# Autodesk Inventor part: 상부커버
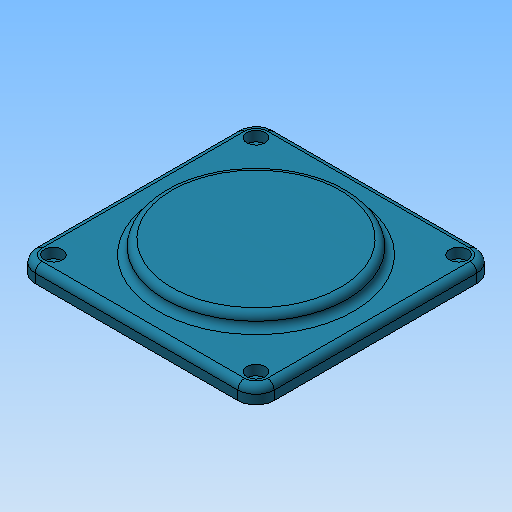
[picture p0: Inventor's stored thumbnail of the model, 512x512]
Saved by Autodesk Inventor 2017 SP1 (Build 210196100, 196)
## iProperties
Created: 2018-09
Part Number: 상부커버
Document SubType Name: Modeling
Density: 2.71 g/cm^3
Material: 알루미늄 6061
Mass: 284.928 g
Surface Area: 255.797 cm^2
Volume: 105.139 cm^3
Appearance: 터키옥색
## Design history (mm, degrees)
sketch "스케치5"
  geometry: L1 (-52.5, -52.5)-(52.5, -52.5); L2 (52.5, -52.5)-(52.5, 52.5); L3 (52.5, 52.5)-(-52.5, 52.5); L4 (-52.5, 52.5)-(-52.5, -52.5); L5 (-52.5, -52.5)-(52.5, 52.5); L6 (52.5, -52.5)-(-52.5, 52.5); 1 further point
  constraints: 12 end point, 2 midpoint, 2 parallel, 1 horizontal, 1 perpendicular
  dimensions: "d35" = 105 distance of L3.end L2.end; "d36" = 105 distance of L2.end L1.end
extrude "돌출4" new body sketch "스케치5" distance "d37" = 7; taper "d38" = 0 deg
fillet "모깎기4" dims "d39" = 8
sketch "스케치2"
  geometry: C1 r 40 at (0, 0); 2 further points
  constraints: 2 coincident, 1 centre point
  dimensions: "d4" = 80 diameter of C1
extrude "돌출3" join sketch "스케치2" distance "d5" = 6; taper "d6" = 0 deg
fillet "모깎기1" dims "d7" = 3
sketch "스케치4"
  geometry: L1 (52.5, -44.5)-(52.5, 44.5) reference; L2 (-44.5, -52.5)-(44.5, -52.5) reference; L3 (-52.5, 44.5)-(-52.5, -44.5) reference; L4 (44.5, 52.5)-(-44.5, 52.5) reference; A1 r 8 centre (44.5, 44.5) between (52.5, 44.5) and (44.5, 52.5) reference; A2 r 8 centre (44.5, -44.5) between (44.5, -52.5) and (52.5, -44.5) reference; A3 r 8 centre (-44.5, -44.5) between (-52.5, -44.5) and (-44.5, -52.5) reference; A4 r 8 centre (-44.5, 44.5) between (-44.5, 52.5) and (-52.5, 44.5) reference; 4 further points
  constraints: 4 coincident
hole "구멍3" sketch "스케치4" at (-44.5, 44.5), (-44.5, -44.5), (44.5, -44.5), (44.5, 44.5) diameter "d43" = 4.5; stored, may be unused: countersink angle "d47" = 90 deg, drill point angle "d49" = 118 deg; dims "d44" = 6, "d45" = 8, "d46" = 4.4, "d48" = 8
fillet "모깎기3" dims "d19" = 3
node "솔리드1"
node "솔리드2"
node "투영된 루프2"
